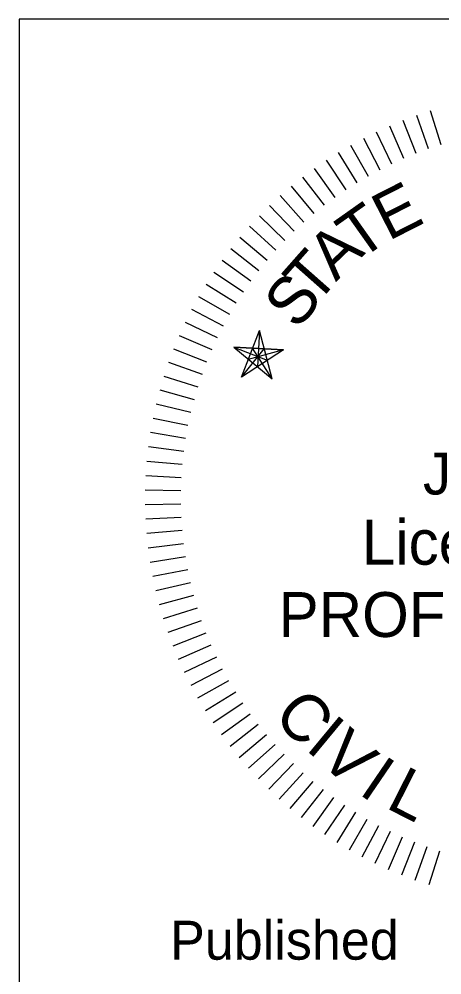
# Model space of a CAD drawing. Extents: x 0.19 to 2.82, y 0.04 to 1.79.
# Drawn here: x 2.2132 to 2.2838, y 0.7579 to 0.9175 of the extents above; entities that cross this region are included whole.
import ezdxf

# ---------------------------------------------------------------- set-up
doc = ezdxf.new("R2010")
doc.units = 0
for name, color, linetype in [('Annotation', 7, 'Continuous'), ('Seal', 7, 'Continuous'), ('Standard Info', 7, 'Continuous')]:
    doc.layers.add(name, color=color, linetype=linetype)

msp = doc.modelspace()

# ---------------------------------------------------------------- linework, layer by layer
at = {"layer": 'Seal'}
for p, q in [((2.28182, 0.90226), (2.28358, 0.89659)), ((2.27726, 0.90065), (2.27942, 0.89513)), ((2.27952, 0.9015), (2.28149, 0.8959)), ((2.27282, 0.89873), (2.27537, 0.89337)), ((2.27502, 0.89973), (2.27738, 0.89429)), ((2.27066, 0.89765), (2.2734, 0.89239)), ((2.26853, 0.8965), (2.27146, 0.89133)), ((2.26442, 0.89396), (2.26771, 0.88902)), ((2.26645, 0.89527), (2.26956, 0.89021)), ((2.26243, 0.89259), (2.26589, 0.88777)), ((2.26049, 0.89114), (2.26412, 0.88645)), ((2.25861, 0.88963), (2.2624, 0.88507)), ((2.25678, 0.88805), (2.26074, 0.88362)), ((2.255, 0.8864), (2.25912, 0.88212)), ((2.25329, 0.88469), (2.25756, 0.88057)), ((2.25164, 0.88293), (2.25605, 0.87895)), ((2.25005, 0.8811), (2.2546, 0.87729)), ((2.24853, 0.87922), (2.25322, 0.87557)), ((2.24708, 0.87729), (2.25189, 0.87381)), ((2.2457, 0.8753), (2.25063, 0.872)), ((2.24439, 0.87327), (2.24944, 0.87015)), ((2.24315, 0.87119), (2.24831, 0.86825)), ((2.24199, 0.86907), (2.24725, 0.86632)), ((2.24091, 0.86691), (2.24626, 0.86434)), ((2.25029, 0.85774), (2.25331, 0.86554)), ((2.25331, 0.86554), (2.25296, 0.85944)), ((2.25543, 0.85743), (2.25331, 0.86554)), ((2.2399, 0.86472), (2.24534, 0.86234)), ((2.23897, 0.86248), (2.24449, 0.8603)), ((2.24902, 0.86276), (2.25732, 0.86229)), ((2.24902, 0.86276), (2.25462, 0.86059)), ((2.25732, 0.86229), (2.24902, 0.86276)), ((2.24902, 0.86276), (2.25543, 0.85743)), ((2.25732, 0.86229), (2.24902, 0.86276)), ((2.24902, 0.86276), (2.25462, 0.86059)), ((2.25029, 0.85774), (2.25412, 0.86245)), ((2.25732, 0.86229), (2.25029, 0.85774)), ((2.25732, 0.86229), (2.25029, 0.85774)), ((2.25732, 0.86229), (2.25029, 0.85774)), ((2.25732, 0.86229), (2.25145, 0.86071)), ((2.25543, 0.85743), (2.25215, 0.8626)), ((2.23812, 0.86022), (2.24372, 0.85824)), ((2.23735, 0.85793), (2.24302, 0.85614)), ((2.23667, 0.85561), (2.24239, 0.85403)), ((2.23607, 0.85327), (2.24184, 0.85189)), ((2.23555, 0.8509), (2.24137, 0.84974)), ((2.23512, 0.84853), (2.24098, 0.84757)), ((2.23477, 0.84613), (2.24066, 0.84538)), ((2.23451, 0.84373), (2.24042, 0.84319)), ((2.23433, 0.84132), (2.24026, 0.84099)), ((2.23424, 0.8389), (2.24018, 0.83879)), ((2.23424, 0.83648), (2.24017, 0.83658)), ((2.23432, 0.83407), (2.24025, 0.83438)), ((2.23449, 0.83166), (2.2404, 0.83218)), ((2.23474, 0.82925), (2.24063, 0.82998)), ((2.23508, 0.82686), (2.24095, 0.8278)), ((2.23551, 0.82448), (2.24133, 0.82563)), ((2.23602, 0.82211), (2.2418, 0.82347)), ((2.23661, 0.81977), (2.24234, 0.82133)), ((2.23729, 0.81745), (2.24296, 0.81921)), ((2.23805, 0.81515), (2.24365, 0.81712)), ((2.23889, 0.81289), (2.24442, 0.81505)), ((2.23982, 0.81065), (2.24526, 0.81301)), ((2.24082, 0.80845), (2.24618, 0.81101)), ((2.2419, 0.80629), (2.24716, 0.80903)), ((2.24305, 0.80416), (2.24821, 0.80709)), ((2.24428, 0.80208), (2.24934, 0.80519)), ((2.24559, 0.80005), (2.25053, 0.80334)), ((2.24696, 0.79806), (2.25178, 0.80152)), ((2.24841, 0.79612), (2.2531, 0.79976)), ((2.24992, 0.79424), (2.25448, 0.79804)), ((2.2515, 0.79241), (2.25592, 0.79637)), ((2.25315, 0.79063), (2.25743, 0.79475)), ((2.25485, 0.78892), (2.25898, 0.79319)), ((2.25662, 0.78727), (2.26059, 0.79168)), ((2.25845, 0.78569), (2.26226, 0.79023)), ((2.26033, 0.78417), (2.26398, 0.78885)), ((2.26226, 0.78271), (2.26574, 0.78752)), ((2.26424, 0.78133), (2.26755, 0.78626)), ((2.26628, 0.78002), (2.2694, 0.78507)), ((2.26835, 0.77878), (2.2713, 0.78394)), ((2.27047, 0.77762), (2.27323, 0.78288)), ((2.27263, 0.77654), (2.2752, 0.78189)), ((2.27483, 0.77553), (2.27721, 0.78097)), ((2.27706, 0.7746), (2.27925, 0.78012)), ((2.27933, 0.77375), (2.28131, 0.77935)), ((2.28162, 0.77299), (2.2834, 0.77865))]:
    msp.add_line(p, q, dxfattribs=at)
at = {"layer": 'Standard Info'}
msp.add_lwpolyline([(2.21319, 0.49428), (2.37266, 0.49428), (2.37266, 0.91754), (2.21319, 0.91754)], close=True, dxfattribs=at)

# ---------------------------------------------------------------- texts
at = {"layer": 'Annotation'}
msp.add_text('Published', height=0.0065, dxfattribs=at).set_placement((2.23839, 0.76045))
at = {"layer": 'Seal'}
for s, rotation, p in [('E', 27.0003, (2.27484, 0.88042)), ('T', 35.3072, (2.27, 0.8771)), ('A', 43.8385, (2.26606, 0.87359)), ('T', 48.535, (2.26269, 0.86961)), ('S', 51.0003, (2.25964, 0.86544)), ('C', 312.2219, (2.25538, 0.80113)), ('I', 320.3933, (2.26081, 0.7956)), ('V', 317.5713, (2.26303, 0.79372)), ('I', 325.7176, (2.26969, 0.78823)), ('L', 333.1234, (2.2742, 0.7859))]:
    msp.add_text(s, height=0.0079, rotation=rotation, dxfattribs=at).set_placement(p)
for s, height, p in [('JOHN DOE', 0.007, (2.28061, 0.83813)), ('JOHN DOE', 0.007, (2.28061, 0.83813)), ('License No. 12345', 0.0075, (2.2704, 0.82641)), ('PROFESSIONAL ENGINEER', 0.0075, (2.25651, 0.81434))]:
    msp.add_text(s, height=height, dxfattribs=at).set_placement(p)

doc.saveas('drawing.dxf')
